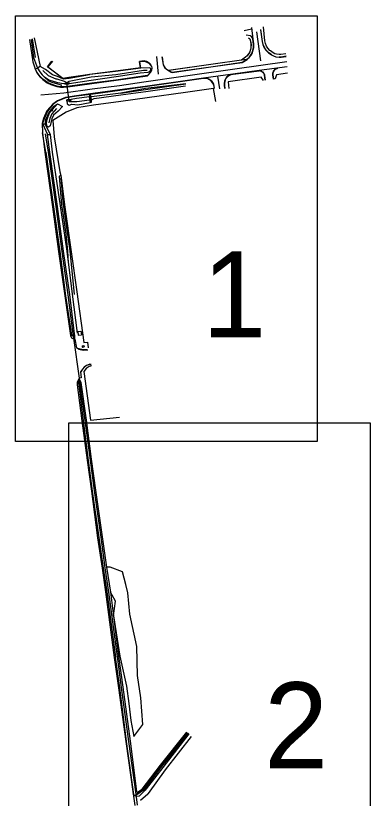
# Model space of a CAD drawing. Extents: x -866693 to -866303, y -1041966 to -1040244.
# Drawn here: x -866434.13 to -866421.78, y -1041212.26 to -1041184.97 of the extents above; entities that cross this region are included whole.
import ezdxf

# ---------------------------------------------------------------- set-up
doc = ezdxf.new("R2010")
doc.units = 0
doc.layers.add('Formát', color=7, linetype='Continuous')
doc.layers.add('Legenda', color=7, linetype='Continuous')

msp = doc.modelspace()

# ---------------------------------------------------------------- linework, layer by layer
at = {"layer": 'Legenda'}
for p, q in [((-866425.917, -1041185.449), (-866426.177, -1041185.507)), ((-866425.867, -1041185.796), (-866425.916, -1041185.382)), ((-866425.75, -1041185.535), (-866425.608, -1041186.547)), ((-866433.651, -1041185.809), (-866433.54, -1041186.586)), ((-866433.596, -1041185.803), (-866433.509, -1041186.438)), ((-866433.447, -1041186.433), (-866433.55, -1041185.78)), ((-866433.494, -1041185.748), (-866433.284, -1041186.745)), ((-866433.509, -1041186.438), (-866433.375, -1041186.803)), ((-866429.787, -1041186.795), (-866429.82, -1041186.572)), ((-866429.78, -1041186.8), (-866429.813, -1041186.577)), ((-866429.226, -1041186.397), (-866429.171, -1041187.02)), ((-866426.087, -1041186.502), (-866426.27, -1041186.527)), ((-866429.458, -1041186.795), (-866429.78, -1041186.8)), ((-866425.658, -1041186.908), (-866426.558, -1041187.026)), ((-866427.026, -1041187.522), (-866427.089, -1041187.088)), ((-866426.558, -1041187.026), (-866426.559, -1041187.022)), ((-866432.553, -1041187.383), (-866432.565, -1041187.453)), ((-866432.347, -1041187.324), (-866432.349, -1041187.3)), ((-866432.271, -1041187.939), (-866432.347, -1041187.323)), ((-866429.612, -1041187.544), (-866428.212, -1041187.353)), ((-866430.476, -1041187.681), (-866429.612, -1041187.544)), ((-866432.347, -1041187.941), (-866432.287, -1041187.941)), ((-866432.269, -1041187.972), (-866432.266, -1041187.939)), ((-866432.011, -1041187.857), (-866432.201, -1041187.896)), ((-866432.839, -1041188.303), (-866432.863, -1041188.266)), ((-866433.2, -1041188.738), (-866433.021, -1041189.123)), ((-866433.102, -1041188.763), (-866432.93, -1041189.114)), ((-866433.083, -1041189.733), (-866433.203, -1041189.054)), ((-866432.331, -1041193.174), (-866432.303, -1041193.6)), ((-866432.129, -1041196.134), (-866431.913, -1041197.698)), ((-866431.974, -1041195.986), (-866431.863, -1041195.97)), ((-866431.974, -1041195.986), (-866431.956, -1041196.115)), ((-866431.972, -1041195.986), (-866431.864, -1041195.971)), ((-866431.972, -1041195.986), (-866431.954, -1041196.113)), ((-866431.956, -1041196.115), (-866431.845, -1041196.099)), ((-866431.954, -1041196.113), (-866431.846, -1041196.098)), ((-866431.864, -1041195.971), (-866431.846, -1041196.098)), ((-866431.863, -1041195.97), (-866431.845, -1041196.099)), ((-866431.817, -1041196.484), (-866431.757, -1041196.476)), ((-866431.817, -1041196.484), (-866431.814, -1041196.528)), ((-866431.816, -1041196.485), (-866431.759, -1041196.478)), ((-866431.816, -1041196.485), (-866431.812, -1041196.526)), ((-866431.814, -1041196.528), (-866431.754, -1041196.52)), ((-866431.812, -1041196.526), (-866431.755, -1041196.518)), ((-866431.759, -1041196.478), (-866431.755, -1041196.518)), ((-866431.757, -1041196.476), (-866431.754, -1041196.52)), ((-866431.749, -1041197.233), (-866431.809, -1041197.3)), ((-866431.666, -1041197.173), (-866431.749, -1041197.233)), ((-866431.55, -1041197.13), (-866431.666, -1041197.173)), ((-866431.55, -1041197.13), (-866431.553, -1041197.128)), ((-866431.865, -1041197.394), (-866431.871, -1041197.392)), ((-866431.809, -1041197.3), (-866431.865, -1041197.394)), ((-866431.939, -1041197.675), (-866431.946, -1041197.778)), ((-866431.946, -1041197.778), (-866431.787, -1041199.099)), ((-866431.913, -1041197.698), (-866431.908, -1041197.759)), ((-866431.908, -1041197.759), (-866431.73, -1041199.088)), ((-866431.864, -1041197.758), (-866431.684, -1041199.081)), ((-866431.787, -1041199.099), (-866431.613, -1041200.479)), ((-866431.73, -1041199.088), (-866431.543, -1041200.47)), ((-866431.684, -1041199.081), (-866431.502, -1041200.437)), ((-866431.613, -1041200.479), (-866431.466, -1041201.546)), ((-866431.543, -1041200.47), (-866431.396, -1041201.529)), ((-866431.502, -1041200.437), (-866431.349, -1041201.513)), ((-866431.466, -1041201.546), (-866431.237, -1041203.168)), ((-866431.396, -1041201.529), (-866431.171, -1041203.154)), ((-866431.349, -1041201.513), (-866431.119, -1041203.143)), ((-866431.237, -1041203.168), (-866431.087, -1041204.23)), ((-866431.171, -1041203.154), (-866431.026, -1041204.222)), ((-866431.119, -1041203.143), (-866430.966, -1041204.202)), ((-866431.087, -1041204.23), (-866430.965, -1041205.065)), ((-866431.026, -1041204.222), (-866430.907, -1041205.068)), ((-866430.841, -1041204.195), (-866430.966, -1041204.202)), ((-866430.966, -1041204.202), (-866430.837, -1041205.075)), ((-866430.414, -1041204.362), (-866430.841, -1041204.195)), ((-866430.296, -1041204.803), (-866430.414, -1041204.362)), ((-866430.231, -1041205.09), (-866430.296, -1041204.803)), ((-866430.965, -1041205.065), (-866430.658, -1041207.341)), ((-866430.907, -1041205.068), (-866430.6, -1041207.32)), ((-866430.837, -1041205.075), (-866430.551, -1041207.309)), ((-866430.662, -1041205.382), (-866430.837, -1041205.075)), ((-866430.163, -1041205.834), (-866430.231, -1041205.09)), ((-866430.723, -1041205.896), (-866430.662, -1041205.382)), ((-866430.723, -1041205.896), (-866430.511, -1041207.303)), ((-866429.919, -1041206.971), (-866430.163, -1041205.834)), ((-866429.894, -1041207.977), (-866429.919, -1041206.971)), ((-866430.506, -1041208.405), (-866430.658, -1041207.341)), ((-866430.6, -1041207.32), (-866430.458, -1041208.39)), ((-866430.551, -1041207.309), (-866430.405, -1041208.385)), ((-866430.511, -1041207.303), (-866430.273, -1041208.355)), ((-866429.773, -1041208.753), (-866429.894, -1041207.977)), ((-866430.28, -1041210.283), (-866430.506, -1041208.405)), ((-866430.458, -1041208.39), (-866430.204, -1041210.273)), ((-866430.405, -1041208.385), (-866430.149, -1041210.267)), ((-866430.273, -1041208.355), (-866430.188, -1041208.953)), ((-866430.188, -1041208.953), (-866430.118, -1041209.551)), ((-866429.709, -1041209.682), (-866429.773, -1041208.753)), ((-866430.118, -1041209.551), (-866430.024, -1041210.109)), ((-866430.024, -1041210.109), (-866429.709, -1041209.682)), ((-866429.086, -1041211.104), (-866428.173, -1041209.953)), ((-866429.077, -1041211.128), (-866428.155, -1041209.966)), ((-866428.12, -1041209.991), (-866429.051, -1041211.146)), ((-866428.104, -1041210.009), (-866429.014, -1041211.179)), ((-866428.92, -1041211.263), (-866428.014, -1041210.106)), ((-866430.014, -1041212.129), (-866430.28, -1041210.283)), ((-866430.204, -1041210.273), (-866429.952, -1041212.112)), ((-866430.149, -1041210.267), (-866429.925, -1041212.02)), ((-866429.725, -1041211.941), (-866429.086, -1041211.104)), ((-866429.708, -1041211.954), (-866429.077, -1041211.128)), ((-866429.051, -1041211.146), (-866429.682, -1041211.972)), ((-866429.014, -1041211.179), (-866429.588, -1041211.93)), ((-866429.51, -1041212.094), (-866428.92, -1041211.263)), ((-866429.889, -1041212.048), (-866429.725, -1041211.941)), ((-866429.889, -1041212.089), (-866429.708, -1041211.954)), ((-866429.682, -1041211.972), (-866429.875, -1041212.114)), ((-866429.653, -1041211.994), (-866429.837, -1041212.188)), ((-866429.621, -1041211.97), (-866429.653, -1041211.994)), ((-866429.588, -1041211.93), (-866429.621, -1041211.97)), ((-866430.004, -1041212.177), (-866430.047, -1041212.105)), ((-866430.002, -1041212.144), (-866430.014, -1041212.129)), ((-866429.91, -1041212.194), (-866430.004, -1041212.177)), ((-866429.972, -1041212.156), (-866430.002, -1041212.144)), ((-866429.933, -1041212.15), (-866429.972, -1041212.156)), ((-866429.952, -1041212.112), (-866429.889, -1041212.089)), ((-866429.952, -1041212.112), (-866429.908, -1041212.498)), ((-866429.898, -1041212.122), (-866429.933, -1041212.15)), ((-866429.925, -1041212.02), (-866429.907, -1041212.045)), ((-866429.837, -1041212.188), (-866429.91, -1041212.194)), ((-866429.907, -1041212.045), (-866429.889, -1041212.048)), ((-866429.875, -1041212.114), (-866429.898, -1041212.122)), ((-866429.786, -1041212.326), (-866429.532, -1041212.106)), ((-866429.532, -1041212.106), (-866429.51, -1041212.094))]:
    msp.add_line(p, q, dxfattribs=at)
for points in [[(-866434.134, -1041184.975), (-866423.634, -1041184.975), (-866423.634, -1041199.825), (-866434.134, -1041199.825)], [(-866432.269, -1041187.351), (-866432.271, -1041187.35), (-866432.274, -1041187.321), (-866432.272, -1041187.321)], [(-866432.348, -1041187.914), (-866432.344, -1041187.94), (-866432.347, -1041187.941)], [(-866431.574, -1041187.765), (-866431.539, -1041188.002), (-866431.488, -1041187.99), (-866431.518, -1041187.753)], [(-866432.672, -1041188.052), (-866432.508, -1041188.136), (-866432.659, -1041188.306), (-866432.811, -1041188.448), (-866432.872, -1041188.577), (-866432.882, -1041188.621), (-866432.936, -1041188.815), (-866432.993, -1041188.857), (-866433.035, -1041188.843), (-866433.056, -1041188.735), (-866433.04, -1041188.597), (-866432.96, -1041188.368)], [(-866432.284, -1041199.17), (-866421.784, -1041199.17), (-866421.784, -1041214.02), (-866432.284, -1041214.02)]]:
    msp.add_lwpolyline(points, close=True, dxfattribs=at)
for points in [[(-866425.605, -1041185.47), (-866425.549, -1041185.881), (-866425.524, -1041185.984), (-866425.491, -1041186.069), (-866425.425, -1041186.174), (-866425.351, -1041186.253), (-866425.327, -1041186.275), (-866425.225, -1041186.343), (-866425.15, -1041186.377), (-866425.073, -1041186.407), (-866424.959, -1041186.425), (-866424.884, -1041186.421), (-866424.71, -1041186.399)], [(-866425.225, -1041186.343), (-866425.223, -1041186.339), (-866425.322, -1041186.27), (-866425.347, -1041186.249), (-866425.419, -1041186.168), (-866425.484, -1041186.067), (-866425.516, -1041185.98), (-866425.543, -1041185.879), (-866425.6, -1041185.461)], [(-866424.721, -1041186.309), (-866424.902, -1041186.33), (-866424.956, -1041186.332), (-866425.054, -1041186.315), (-866425.111, -1041186.3), (-866425.169, -1041186.271), (-866425.26, -1041186.206), (-866425.287, -1041186.187), (-866425.356, -1041186.108), (-866425.401, -1041186.034), (-866425.437, -1041185.947), (-866425.461, -1041185.855), (-866425.502, -1041185.37)], [(-866429.042, -1041186.407), (-866428.999, -1041186.692), (-866428.95, -1041186.78), (-866428.895, -1041186.833), (-866428.788, -1041186.901), (-866428.721, -1041186.94), (-866428.685, -1041186.951), (-866427.252, -1041186.75), (-866426.245, -1041186.607), (-866426.077, -1041186.503), (-866426, -1041186.435), (-866425.925, -1041186.336), (-866425.89, -1041186.271), (-866425.862, -1041186.164), (-866425.844, -1041186.085), (-866425.844, -1041185.961), (-866425.867, -1041185.796), (-866425.898, -1041185.733), (-866425.933, -1041185.692), (-866425.958, -1041185.674), (-866426.108, -1041185.651)], [(-866426.027, -1041185.752), (-866425.981, -1041185.781), (-866425.955, -1041185.86), (-866425.941, -1041185.982), (-866425.945, -1041186.092), (-866425.956, -1041186.152), (-866425.981, -1041186.23), (-866426.018, -1041186.292), (-866426.082, -1041186.372), (-866426.134, -1041186.424), (-866426.272, -1041186.525), (-866427.262, -1041186.665), (-866428.809, -1041186.882)], [(-866425.852, -1041186.085), (-866425.849, -1041185.963), (-866425.872, -1041185.797), (-866425.898, -1041185.739), (-866425.936, -1041185.695), (-866425.959, -1041185.677), (-866426.102, -1041185.655)], [(-866426.027, -1041185.749), (-866425.98, -1041185.78), (-866425.953, -1041185.859), (-866425.938, -1041185.981)], [(-866425.938, -1041185.981), (-866425.94, -1041186.093), (-866425.955, -1041186.153), (-866425.979, -1041186.232), (-866426.014, -1041186.294), (-866426.075, -1041186.374), (-866426.134, -1041186.426), (-866426.27, -1041186.527), (-866427.261, -1041186.668), (-866428.806, -1041186.883)], [(-866426.087, -1041186.502), (-866426.081, -1041186.497), (-866426.006, -1041186.43), (-866425.933, -1041186.331), (-866425.897, -1041186.27), (-866425.852, -1041186.085)], [(-866433.54, -1041186.586), (-866433.46, -1041186.832), (-866433.396, -1041186.965), (-866433.288, -1041187.11), (-866433.192, -1041187.203), (-866433.033, -1041187.318), (-866432.907, -1041187.379), (-866432.701, -1041187.448), (-866432.576, -1041187.468), (-866432.466, -1041187.468), (-866432.241, -1041187.449), (-866431.483, -1041187.345), (-866430.63, -1041187.226), (-866429.543, -1041187.068), (-866429.428, -1041186.941), (-866429.392, -1041186.874), (-866429.384, -1041186.797), (-866429.397, -1041186.745), (-866429.425, -1041186.697), (-866429.475, -1041186.641), (-866429.515, -1041186.609), (-866429.583, -1041186.575), (-866429.66, -1041186.551), (-866429.82, -1041186.572)], [(-866433.258, -1041187.739), (-866432.455, -1041187.66), (-866431.47, -1041187.524), (-866430.516, -1041187.406), (-866429.666, -1041187.28), (-866428.22, -1041187.069), (-866426.502, -1041186.825), (-866424.694, -1041186.578)], [(-866429.78, -1041186.8), (-866430.652, -1041186.917), (-866431.554, -1041187.031), (-866432.277, -1041187.134), (-866432.496, -1041187.164), (-866433.022, -1041186.76), (-866432.869, -1041186.566)], [(-866432.857, -1041186.563), (-866433.011, -1041186.763), (-866432.494, -1041187.155), (-866432.298, -1041187.128), (-866431.706, -1041187.046)], [(-866429.813, -1041186.577), (-866429.656, -1041186.561), (-866429.587, -1041186.583), (-866429.519, -1041186.615), (-866429.479, -1041186.646), (-866429.431, -1041186.701), (-866429.403, -1041186.746), (-866429.391, -1041186.796), (-866429.4, -1041186.872), (-866429.436, -1041186.939), (-866429.547, -1041187.064), (-866430.642, -1041187.221)], [(-866429.035, -1041186.406), (-866428.994, -1041186.691), (-866428.943, -1041186.777), (-866428.891, -1041186.829), (-866428.809, -1041186.882), (-866428.806, -1041186.883), (-866428.783, -1041186.896), (-866428.781, -1041186.893), (-866428.738, -1041186.916), (-866428.683, -1041186.939), (-866428.685, -1041186.944), (-866427.253, -1041186.744), (-866426.246, -1041186.598), (-866426.087, -1041186.502)], [(-866424.71, -1041186.392), (-866424.885, -1041186.416), (-866424.96, -1041186.419), (-866424.959, -1041186.425)], [(-866433.46, -1041186.832), (-866433.375, -1041186.803), (-866433.289, -1041186.936), (-866433.216, -1041187.034), (-866433.126, -1041187.123), (-866432.994, -1041187.246), (-866432.871, -1041187.297), (-866432.683, -1041187.355), (-866432.553, -1041187.383)], [(-866430.642, -1041187.221), (-866431.486, -1041187.331), (-866432.242, -1041187.437), (-866432.466, -1041187.455), (-866432.573, -1041187.453), (-866432.696, -1041187.433), (-866432.9, -1041187.366), (-866433.024, -1041187.306), (-866433.184, -1041187.189), (-866433.278, -1041187.099), (-866433.384, -1041186.956), (-866433.46, -1041186.832)], [(-866431.559, -1041187.036), (-866432.275, -1041187.162), (-866432.474, -1041187.189), (-866432.674, -1041187.097), (-866432.853, -1041187.043), (-866433.095, -1041186.851), (-866433.284, -1041186.745), (-866433.375, -1041186.803)], [(-866424.685, -1041186.755), (-866425.659, -1041186.89), (-866426.576, -1041187.016), (-866427.598, -1041187.158), (-866428.228, -1041187.247), (-866429.628, -1041187.441), (-866430.506, -1041187.562), (-866431.446, -1041187.693), (-866432.017, -1041187.77), (-866432.396, -1041187.828), (-866432.678, -1041187.944), (-866432.843, -1041188.063), (-866433.044, -1041188.297), (-866433.166, -1041188.565), (-866433.211, -1041188.733), (-866433.203, -1041189.054), (-866433.114, -1041189.728), (-866432.847, -1041191.643), (-866432.637, -1041193.198), (-866432.421, -1041194.745), (-866432.227, -1041196.129), (-866432.191, -1041196.208), (-866432.142, -1041196.234), (-866432.077, -1041196.249), (-866432.01, -1041196.556), (-866431.93, -1041196.599), (-866431.884, -1041196.614), (-866431.77, -1041196.634), (-866431.622, -1041196.625)], [(-866433.191, -1041186.882), (-866433.006, -1041187.06), (-866432.73, -1041187.182), (-866432.703, -1041187.18), (-866432.444, -1041187.26), (-866432.349, -1041187.3), (-866432.275, -1041187.263), (-866431.504, -1041187.112), (-866430.641, -1041187.027), (-866429.677, -1041186.878), (-866429.557, -1041186.879)], [(-866429.458, -1041186.795), (-866429.432, -1041186.843), (-866429.467, -1041186.926), (-866429.527, -1041186.957), (-866429.796, -1041186.974), (-866430.635, -1041187.102), (-866431.5, -1041187.237), (-866432.269, -1041187.351)], [(-866429.787, -1041186.795), (-866430.66, -1041186.912), (-866431.561, -1041187.026), (-866431.706, -1041187.046)], [(-866425.437, -1041187.222), (-866425.46, -1041187.062), (-866425.462, -1041187.051), (-866425.472, -1041187.015), (-866425.479, -1041186.999), (-866425.49, -1041186.98), (-866425.517, -1041186.95), (-866425.546, -1041186.931), (-866425.57, -1041186.919), (-866425.606, -1041186.909), (-866425.659, -1041186.89)], [(-866425.658, -1041186.908), (-866425.658, -1041186.908), (-866425.659, -1041186.902), (-866425.659, -1041186.89)], [(-866425.441, -1041187.222), (-866425.468, -1041187.051), (-866425.484, -1041187.006), (-866425.523, -1041186.955), (-866425.572, -1041186.927), (-866425.609, -1041186.915), (-866425.659, -1041186.902)], [(-866425.033, -1041186.818), (-866425.052, -1041186.822), (-866425.077, -1041186.83), (-866425.097, -1041186.842), (-866425.118, -1041186.857), (-866425.136, -1041186.874), (-866425.156, -1041186.894), (-866425.166, -1041186.915), (-866425.183, -1041186.954), (-866425.186, -1041186.977), (-866425.185, -1041187.035), (-866425.163, -1041187.183)], [(-866425.033, -1041186.818), (-866425.033, -1041186.824), (-866425.074, -1041186.837), (-866425.093, -1041186.848), (-866425.115, -1041186.863), (-866425.149, -1041186.899), (-866425.175, -1041186.956), (-866425.178, -1041186.978), (-866425.177, -1041187.034), (-866425.156, -1041187.179)], [(-866427.216, -1041187.51), (-866427.227, -1041187.435), (-866427.241, -1041187.379), (-866427.266, -1041187.323), (-866427.311, -1041187.267), (-866427.361, -1041187.224), (-866427.406, -1041187.197), (-866427.448, -1041187.179), (-866427.491, -1041187.167), (-866427.533, -1041187.16), (-866427.577, -1041187.163), (-866427.597, -1041187.165), (-866427.599, -1041187.17), (-866428.24, -1041187.261), (-866429.626, -1041187.454), (-866430.505, -1041187.578), (-866431.439, -1041187.706), (-866432.013, -1041187.784), (-866432.392, -1041187.842), (-866432.672, -1041187.958), (-866432.712, -1041187.982), (-866432.834, -1041188.076), (-866433.031, -1041188.304), (-866433.147, -1041188.575), (-866433.2, -1041188.738), (-866433.211, -1041188.733)], [(-866432.423, -1041187.337), (-866432.474, -1041187.348), (-866432.671, -1041187.321), (-866432.855, -1041187.259), (-866432.984, -1041187.227), (-866433.126, -1041187.123)], [(-866427.208, -1041187.509), (-866427.218, -1041187.433), (-866427.232, -1041187.375), (-866427.262, -1041187.319), (-866427.305, -1041187.262), (-866427.357, -1041187.22), (-866427.402, -1041187.193), (-866427.443, -1041187.174), (-866427.49, -1041187.16), (-866427.533, -1041187.154), (-866427.598, -1041187.158)], [(-866426.576, -1041187.016), (-866426.649, -1041187.033), (-866426.714, -1041187.061), (-866426.777, -1041187.111), (-866426.826, -1041187.175), (-866426.861, -1041187.26), (-866426.873, -1041187.336), (-866426.87, -1041187.401), (-866426.857, -1041187.515)], [(-866426.559, -1041187.022), (-866426.577, -1041187.024), (-866426.646, -1041187.038), (-866426.712, -1041187.068), (-866426.772, -1041187.114), (-866426.822, -1041187.182), (-866426.852, -1041187.26), (-866426.862, -1041187.337), (-866426.859, -1041187.403), (-866426.85, -1041187.514)], [(-866425.502, -1041187.231), (-866425.589, -1041187.116), (-866426.733, -1041187.28), (-866426.707, -1041187.514)], [(-866424.663, -1041186.981), (-866425.049, -1041187.038), (-866425.101, -1041187.176), (-866425.15, -1041187.183)], [(-866432.274, -1041187.321), (-866432.423, -1041187.337), (-866432.418, -1041187.366), (-866432.271, -1041187.35)], [(-866432.423, -1041187.337), (-866432.365, -1041187.326), (-866432.347, -1041187.324), (-866432.333, -1041187.323), (-866432.272, -1041187.321)], [(-866428.212, -1041187.353), (-866429.615, -1041187.513), (-866430.476, -1041187.681), (-866431.406, -1041187.79), (-866431.512, -1041187.8)], [(-866431.399, -1041187.864), (-866430.477, -1041187.735), (-866429.597, -1041187.619), (-866428.218, -1041187.421)], [(-866427.169, -1041187.972), (-866427.248, -1041187.519), (-866428.215, -1041187.649), (-866429.558, -1041187.838), (-866430.472, -1041187.963), (-866431.425, -1041188.092), (-866432.007, -1041188.188), (-866432.381, -1041188.34), (-866432.834, -1041188.626), (-866432.793, -1041189.201), (-866432.592, -1041190.424), (-866432.563, -1041190.547), (-866432.524, -1041190.815), (-866432.428, -1041191.574), (-866432.203, -1041193.213), (-866432.008, -1041194.601), (-866431.761, -1041196.372), (-866431.634, -1041196.355), (-866431.61, -1041196.558)], [(-866432.342, -1041187.94), (-866432.198, -1041187.923), (-866432.201, -1041187.896), (-866432.348, -1041187.914)], [(-866432.347, -1041187.941), (-866432.342, -1041188.052), (-866432.273, -1041188.095), (-866432.173, -1041188.065), (-866431.964, -1041188.085), (-866431.539, -1041188.002)], [(-866432.287, -1041187.941), (-866432.266, -1041187.939), (-866432.251, -1041187.935), (-866432.228, -1041187.934), (-866432.196, -1041187.921)], [(-866432.269, -1041187.972), (-866432.004, -1041187.966), (-866431.558, -1041187.913)], [(-866432.198, -1041187.923), (-866432.196, -1041187.921), (-866432.201, -1041187.896)], [(-866431.568, -1041187.808), (-866432.011, -1041187.857)], [(-866431.574, -1041187.765), (-866431.558, -1041187.913), (-866431.539, -1041188.002)], [(-866431.488, -1041187.99), (-866431.495, -1041187.906), (-866431.518, -1041187.753)], [(-866431.495, -1041187.906), (-866431.399, -1041187.864)], [(-866433.2, -1041188.738), (-866433.102, -1041188.763), (-866433.087, -1041188.589), (-866432.979, -1041188.359), (-866432.788, -1041188.128), (-866432.672, -1041188.052)], [(-866432.711, -1041188.215), (-866432.875, -1041188.401), (-866432.94, -1041188.56), (-866432.976, -1041188.713)], [(-866433.112, -1041189.09), (-866432.999, -1041189.73), (-866432.737, -1041191.628), (-866432.524, -1041193.194), (-866432.32, -1041194.708), (-866432.144, -1041196.062), (-866432.129, -1041196.134)], [(-866432.077, -1041196.249), (-866432.077, -1041196.118), (-866432.087, -1041196.065), (-866432.247, -1041194.696), (-866432.463, -1041193.19), (-866432.681, -1041191.622), (-866432.941, -1041189.736), (-866433.021, -1041189.123), (-866432.93, -1041189.114), (-866432.861, -1041189.734), (-866432.587, -1041191.605), (-866432.357, -1041193.179), (-866432.165, -1041194.686), (-866431.988, -1041196.047)], [(-866433.083, -1041189.733), (-866432.816, -1041191.644), (-866432.596, -1041193.195), (-866432.398, -1041194.739), (-866432.186, -1041196.118), (-866432.148, -1041196.142), (-866432.123, -1041196.138), (-866432.112, -1041196.125), (-866432.087, -1041196.065)], [(-866432.563, -1041190.547), (-866432.622, -1041190.566), (-866432.541, -1041191.584), (-866432.491, -1041191.863), (-866432.382, -1041192.589), (-866432.331, -1041193.174)], [(-866432.563, -1041190.629), (-866432.489, -1041191.46), (-866432.251, -1041193.178), (-866432.095, -1041194.701)], [(-866432.01, -1041196.556), (-866432.005, -1041196.552), (-866431.926, -1041196.591)], [(-866431.639, -1041196.62), (-866431.768, -1041196.628), (-866431.884, -1041196.605), (-866431.926, -1041196.591)], [(-866431.553, -1041197.128), (-866431.669, -1041197.169), (-866431.752, -1041197.227), (-866431.812, -1041197.295), (-866431.871, -1041197.392), (-866431.854, -1041197.605), (-866431.921, -1041197.617), (-866431.99, -1041197.755), (-866431.992, -1041197.849), (-866431.825, -1041199.101), (-866431.641, -1041200.467), (-866431.497, -1041201.556), (-866431.282, -1041203.177), (-866431.118, -1041204.231), (-866431.002, -1041205.056), (-866430.699, -1041207.352), (-866430.55, -1041208.409), (-866430.303, -1041210.281), (-866430.047, -1041212.105), (-866429.988, -1041212.511)], [(-866431.525, -1041197.113), (-866431.516, -1041197.189), (-866431.572, -1041197.207), (-866431.679, -1041197.274), (-866431.755, -1041197.376), (-866431.526, -1041199.08), (-866430.522, -1041198.97)], [(-866431.939, -1041197.675), (-866431.897, -1041197.681), (-866431.864, -1041197.758)]]:
    msp.add_lwpolyline(points, dxfattribs=at)

# ---------------------------------------------------------------- texts
at = {"layer": 'Formát'}
for s, p in [('1', (-866427.641, -1041196.192)), ('2', (-866425.483, -1041211.216))]:
    msp.add_text(s, height=3, dxfattribs=at).set_placement(p)

doc.saveas('drawing.dxf')
